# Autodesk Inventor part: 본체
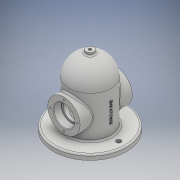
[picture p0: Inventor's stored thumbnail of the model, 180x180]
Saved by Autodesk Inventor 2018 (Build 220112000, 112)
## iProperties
Created: 2019-11
Part Number: 본체
Material: 일반
Document SubType Name: Modeling
Designer: USER
Density: 1 g/cm^3
Appearance: 기본값
Author: USER
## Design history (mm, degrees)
sketch "스케치1"
  geometry: C1 r 70 at (0, 0); 1 further point
  constraints: 1 centre point, 1 coincident
  dimensions: "d0" = 140 diameter of C1
extrude "돌출1" new body sketch "스케치1" distance "d1" = 10; taper "d2" = 0 deg
sketch "스케치2"
  geometry: C1 r 4.5 at (55, 0); 1 further point
  constraints: 1 centre point, 1 horizontal alignment
  dimensions: "d3" = 9 diameter of C1; "d4" = 55 distance of point (0, 0) C1.centre
extrude "돌출2" cut sketch "스케치2" extent not by distance; stored distance "d5" = 10; taper "d6" = 0 deg
sketch "스케치4"
  geometry: C1 r 40 at (0, 0); 1 further point
  constraints: 1 centre point, 1 coincident
  dimensions: "d7" = 80 diameter of C1
extrude "돌출3" join sketch "스케치4" distance "d8" = 80; taper "d9" = 0 deg
sketch "스케치5"
  geometry: L1 (40, 90)-(-40, 90) reference; L2 (0, 90)-(0, 130); A1 r 40 centre (0, 90) between (0, 130) and (-40, 90); 1 further point
  constraints: 3 point on circle, 2 end point, 1 centre point, 1 midpoint, 1 point on line, 1 vertical
  dimensions: "d10" = 40 distance of L2.start L2.end; "d12" = 40 radius of A1
revolve "회전1" sketch "스케치5" stored, may be unused: angle "d13" = 90 deg
node "작업 평면2"
sketch "스케치6"
  geometry: C1 r 7.5 at (0, 0); 1 further point
  constraints: 1 centre point, 1 coincident
  dimensions: "d16" = 15 diameter of C1
extrude "돌출4" join sketch "스케치6" distance "d17" = 90; taper "d18" = 0 deg
sketch "스케치7"
  geometry: 2 further points
  constraints: 1 coincident
hole "구멍1" sketch "스케치7" at (0, 0) diameter "d19" = 5.188; stored, may be unused: countersink angle "d23" = 90 deg, drill point angle "d25" = 118 deg; dims "d20" = 12, "d21" = 4, "d22" = 2, "d24" = 192.25
sketch "스케치10"
  geometry: C1 r 2.594 at (0, 0) reference; C2 r 30 at (0, 0); 1 further point
  constraints: 1 centre point, 1 coincident
  dimensions: "d26" = 60 diameter of C2
extrude "돌출5" cut sketch "스케치10" distance "d27" = 90; taper "d28" = 0 deg
sketch "스케치11"
  geometry: L1 (-2.594, 90)-(2.594, 90) reference; L2 (0, 90)-(0, 120); L3 (30, 0)-(30, 90) reference; L4 (30, 90)-(-30, 90) reference; A1 r 30 centre (0, 90) between (0, 120) and (-30, 90); 1 further point
  constraints: 3 point on circle, 2 end point, 2 point on line, 1 centre point, 1 midpoint, 1 vertical
  dimensions: "d30" = 30 distance of L2.start L2.end; "d31" = 30 radius of A1
revolve "회전2" sketch "스케치11" stored, may be unused: angle "d32" = 90 deg
node "작업 평면4"
sketch "스케치14"
  geometry: L1 (-70, 0)-(70, 0) reference; C1 r 31 at (0, 50); 1 further point
  constraints: 1 centre point, 1 vertical alignment
  dimensions: "d34" = 62 diameter of C1; "d35" = 50 distance from line of L1 C1.centre
extrude "돌출6" join sketch "스케치14" stored distance "d36" = 90; taper "d37" = 0 deg
sketch "스케치15"
  geometry: C1 r 31 at (0, 0) reference; C2 r 16.5 at (0, 0); 1 further point
  constraints: 1 centre point, 1 coincident
  dimensions: "d38" = 33 diameter of C2
extrude "돌출7" cut sketch "스케치15" extent not by distance; stored distance "d39" = 90; taper "d40" = 0 deg
sketch "스케치16"
  geometry: C1 r 16.5 at (0, 0) reference; C2 r 20 at (0, 0); 1 further point
  constraints: 1 centre point, 1 coincident
  dimensions: "d41" = 40 diameter of C2
extrude "돌출8" cut sketch "스케치16" distance "d42" = 15; taper "d43" = 0 deg
sketch "스케치17"
  geometry: C1 r 20 at (0, 0) reference; 2 further points
  constraints: 1 vertical alignment
  dimensions: "d44" = 26 distance of C1.centre point (0, 26)
hole "구멍2" sketch "스케치17" at (0, 26) diameter "d45" = 3.242; stored, may be unused: countersink angle "d49" = 90 deg, drill point angle "d51" = 118 deg; dims "d46" = 8, "d47" = 4, "d48" = 2, "d50" = 10
fillet "모깎기1" dims "d55" = 3
fillet "모깎기2" dims "d56" = 3
fillet "모깎기3" dims "d57" = 0.3
chamfer "모따기1" distance "d58" = 1; stored, may be unused: second distance "d59" = 2, angle "d60" = 45 deg
sketch "스케치19"
  geometry: 1 further point
node "작업 평면5"
sketch "스케치20"
  geometry: L1 (-70, -10)-(70, -10) reference; 2 further points
  constraints: 1 vertical alignment, 1 other
  dimensions: "d61" = 50 distance from line of L1 point (0, 40)
feature "엠보싱1" sketch "스케치20" dims "d1" = 10, "d10" = 40, "d12" = 40, "d62" = 0.5, "d63" = 0
node "솔리드1"
mirror "미러1"
mirror "미러2"
mirror "미러3"
pattern_circular "원형 패턴1" dims angle "d53" = 360 deg
mirror "미러4"
other parameters: "d15" = -135
